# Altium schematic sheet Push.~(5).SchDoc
size A4; SheetNumber: 1; SheetTotal: 1
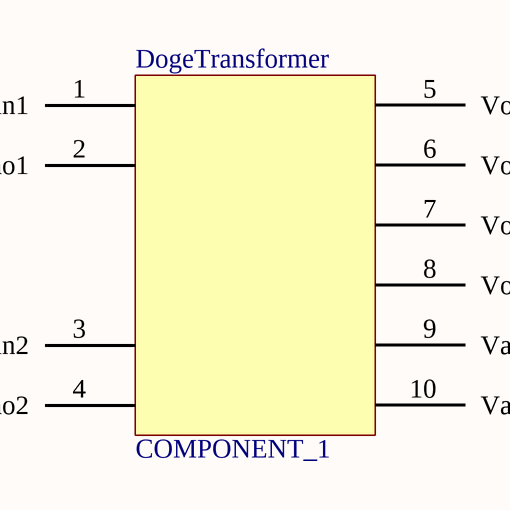
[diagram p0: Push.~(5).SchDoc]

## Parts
DogeTransformer  COMPONENT_1  [transformer]

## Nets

Not connected (* = marked no-connect by the designer): DogeTransformer 1(Vin1) 2(Vino1) 3(Vin2) 4(Vino2) 5(Vout1) 6(Vouto1) 7(Vout2) 8(Vouto2) 9(Vaux) 10(Vauxo)

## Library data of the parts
DogeTransformer = COMPONENT_1: Doge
